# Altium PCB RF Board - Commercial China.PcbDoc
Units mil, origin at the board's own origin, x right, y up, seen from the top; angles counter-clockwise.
Board outline 2000 x 1000 mil, 2 copper layers (Top Layer, Bottom Layer); 17 components, 17 nets, 58 pads, 9 vias.
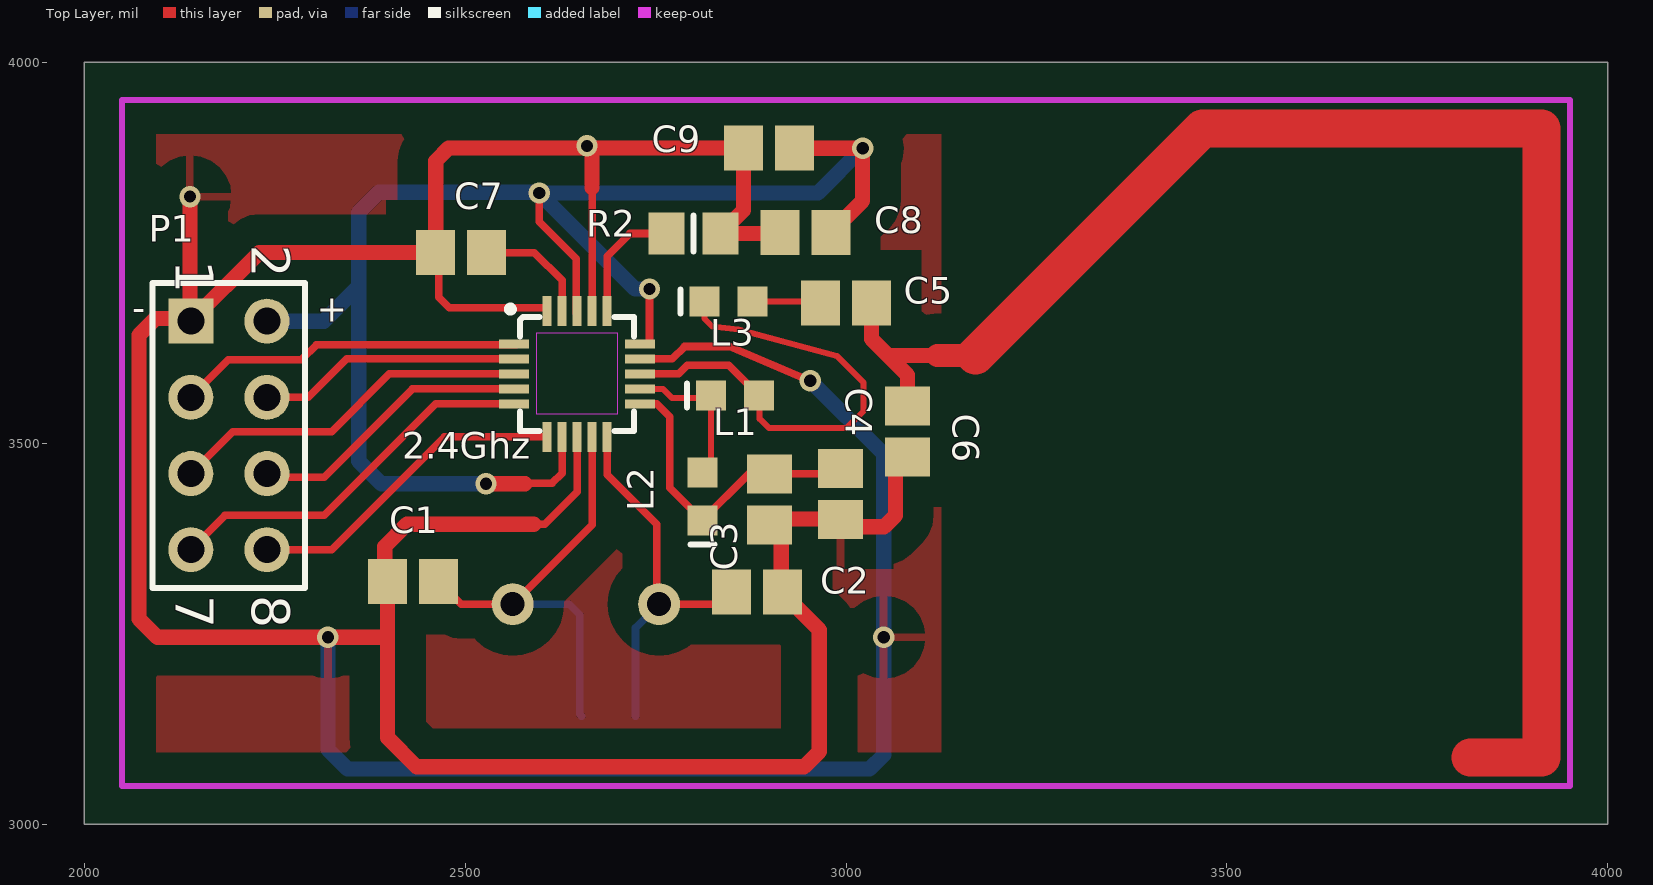
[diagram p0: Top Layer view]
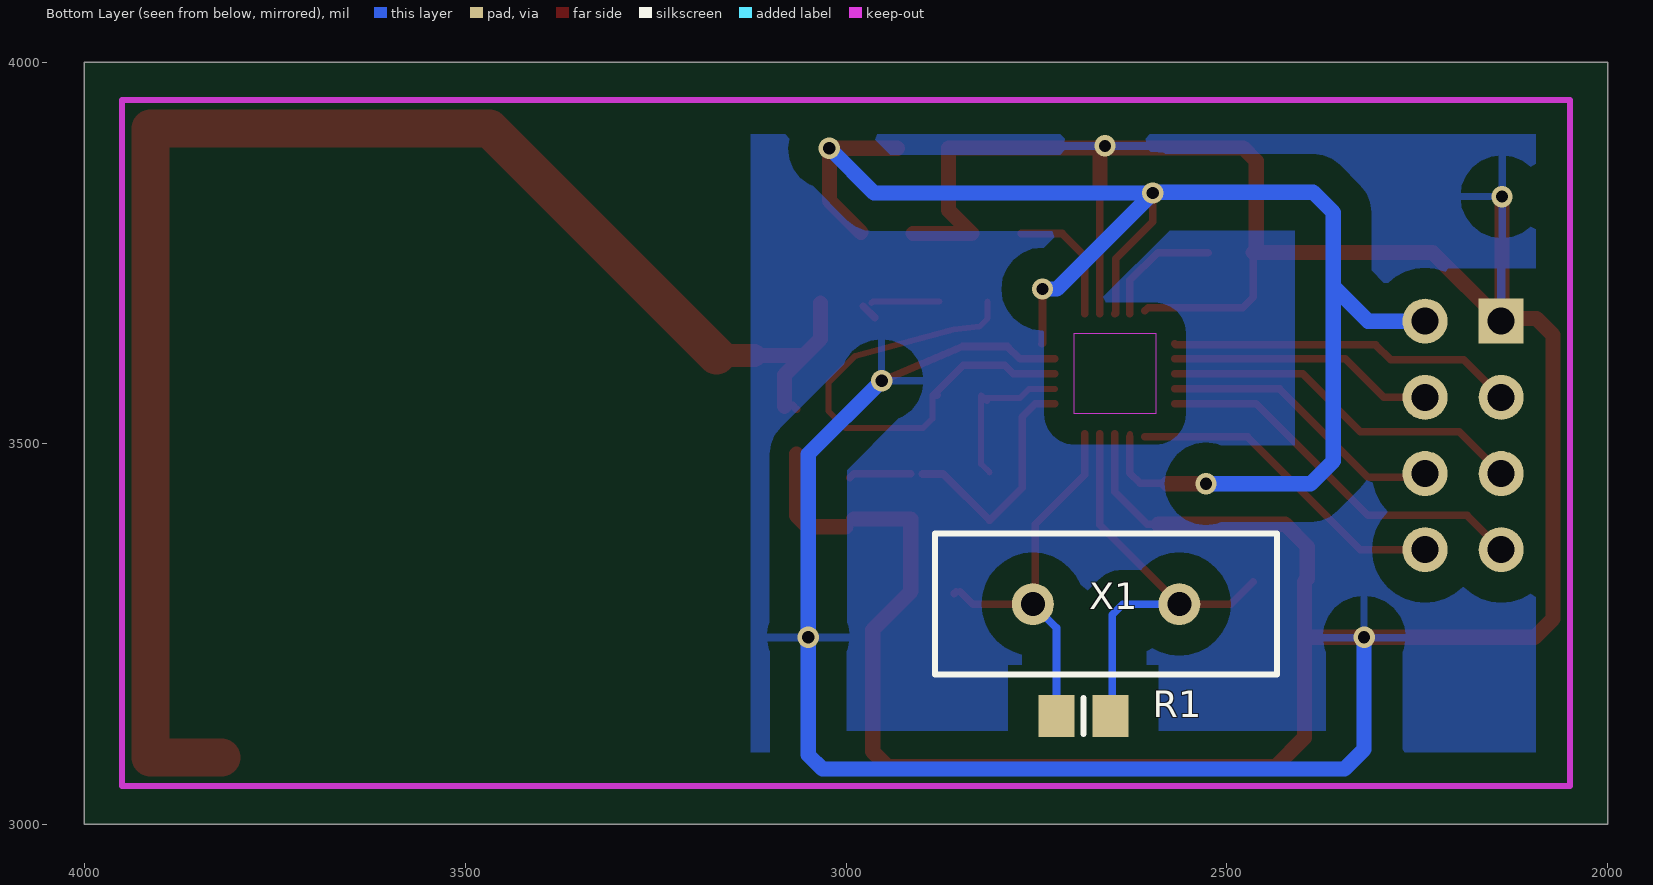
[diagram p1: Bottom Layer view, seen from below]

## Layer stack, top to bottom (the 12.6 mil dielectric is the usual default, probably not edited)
Top Layer: signal copper 1.4
Dielectric: dielectric 12.6, FR-4, Dk 4.8
Bottom Layer: signal copper 1.4

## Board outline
2000,3000 4000,3000 4000,4000 2000,4000

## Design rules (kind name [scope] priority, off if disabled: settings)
Clearance "Polygon Clearance" [InPolygon] p1: gap=40
Clearance [All] p2: gap=8.1
HoleSize [All] p1: absolutevalues=TRUE maxlimit=100 minlimit=16 maxpercent=80.000 minpercent=20.000
MinimumAnnularRing [All] p1: minimumring=6
PolygonConnect [All] p1: connectstyle=Relief reliefconductorwidth=10 reliefentries=4 polygonreliefangle="90 Angle"
RoutingVias [All] p1: holewidth=16 width=28 viastyle="Through Hole" minholewidth=16 minwidth=27 maxholewidth=16 maxwidth=35
SilkscreenOverComponentPads [All] p1: minsilkscreentomaskgap=10
SolderMaskExpansion [All] p1: expansion=4
Width [All] p1: maxlimit=50 minlimit=8 preferedwidth=8
26 further rules are at their usual default settings.

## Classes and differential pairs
component class "2.4Ghz Chip Board": P1
net class SPI[3..0]: SPI0 SPI1 SPI2 SPI3

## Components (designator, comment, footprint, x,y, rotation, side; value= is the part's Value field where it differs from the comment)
2.4Ghz "nRF24L01+" nRF24L01+ 2576.16,3630.12 r0 top (schematic designator "2.4Ghz Chip")
C1 "Cap Semi" CAPC2012N 2431.81,3318.02 r0 top
C2 "Cap Semi" CAPC2012N 2883.35,3304.68 r180 top
C3 "Cap Semi" CAPC2012N 2899.64,3425.9 r90 top
C4 "Cap Semi" CAPC2012N 2992.87,3433.15 r90 top
C5 "Cap Semi" CAPC2012N 3000.12,3683.85 r180 top
C6 "Cap Semi" CAPC2012N 3080.62,3514.92 r90 top
C7 "Cap Semi" CAPC2012N 2495,3750 r0 top
C8 "Cap Semi" CAPC2012N 2946.88,3776.47 r0 top
C9 "Cap Semi" CAPC2012N 2899.02,3887.01 r0 top
L1 "Inductor" INDC1608N 2854.06,3562.65 r0 top
L2 "Inductor" INDC1608N 2811.58,3430.04 r90 top
L3 "Inductor" INDC1608N 2845.77,3685.93 r0 top
P1 "Header 4X2" HDR2X4 2140,3660 r270 top
R1 "Res2" RESC2012N 2688.35,3141.5 r0 bottom
R2 "Res3" RESC2012N 2799.53,3775 r0 top
X1 "16Mhz" "HC-49U - Through Hole" 2658.63,3288.52 r0 bottom

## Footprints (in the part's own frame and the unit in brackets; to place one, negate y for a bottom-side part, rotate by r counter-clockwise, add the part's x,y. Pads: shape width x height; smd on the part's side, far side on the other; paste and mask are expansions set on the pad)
CAPC2012N [mm] "Chip Capacitor, Body 2.0x1.3mm, IPC Medium Density"
  rect 1.3x1.5 smd: 1(-0.85,0) 2(0.85,0)
  body extent -1.1,-0.72 1.1,0.72, height 1.1
"HC-49U - Through Hole" [mm] "Quartz Crystal, Thru-Hole; 2 Leads; Body 11.35 x 4.65 x 13.46 mm (LxWxH max)"
  round 1.4 hole 0.8: 1(-2.44,0) 2(2.44,0)
  silkscreen extent -5.7,-2.35 5.7,2.35
HDR2X4 [mm] "Connector; Header; 4x2 Position"
  rect 1.5x1.5 hole 0.9: 1(0,0)
  round 1.5 hole 0.9: 2(0,2.54) 3(2.54,0) 4(2.54,2.54) 5(5.08,0) 6(5.08,2.54) 7(7.62,0) 8(7.62,2.54)
  silkscreen extent -1.27,-1.27 8.89,3.81
INDC1608N [mm] "Chip Inductor, Body 1.6x0.8mm, IPC Medium Density"
  rect 1x1 smd: 1(-0.8,0) 2(0.8,0)
  silkscreen extent -1.6,-0.4 -1.6,0.4, body extent -0.87,-0.48 0.87,0.48, height 0.71
nRF24L01+ [mm]
  rect 1x0.29 smd: 1(-0.3,0) 2(-0.3,-0.5) 3(-0.3,-1) 4(-0.3,-1.5) 5(-0.3,-2) 11(3.9,-2) 12(3.9,-1.5) 13(3.9,-1) 14(3.9,-0.5) 15(3.9,0)
  rect 0.29x1 smd: 6(0.8,-3.1) 7(1.3,-3.1) 8(1.8,-3.1) 9(2.3,-3.1) 10(2.8,-3.1) 16(2.8,1.1) 17(2.3,1.1) 18(1.8,1.1) 19(1.3,1.1) 20(0.8,1.1)
  Keep-Out Layer region: 0.447,-2.334 3.152,-2.334 3.152,0.357 0.447,0.357
  silkscreen extent -0.49,-2.9 3.7,1.22
RESC2012N [mm] "Chip Resistor, Body 2.0x1.3mm, IPC Medium Density"
  rect 1.2x1.4 smd: 1(-0.9,0) 2(0.9,0)
  silkscreen extent 0,-0.6 0,0.6, body extent -1.07,-0.7 1.07,0.7, height 0.65

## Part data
C1 C2 C3 C4 C5 C6 C7 C8 C9: "Capacitor (Semiconductor SIM Model)"
P1: "Header, 4-Pin, Dual row"
R1 R2: "Resistor"
X1: library part XTAL, "Crystal Oscillator"

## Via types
v1: diameter 28, hole 16, Top Layer to Bottom Layer, 9 vias

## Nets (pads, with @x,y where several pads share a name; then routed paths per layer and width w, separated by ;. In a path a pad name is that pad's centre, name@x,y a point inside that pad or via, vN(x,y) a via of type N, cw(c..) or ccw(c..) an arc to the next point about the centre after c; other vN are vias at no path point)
3.3VCC: 2.4Ghz.7 2.4Ghz.15 2.4Ghz.18 C8.2 C9.2 P1.2 | length 2171.9
  Top Layer w8: 2.4Ghz.7 2.4Ghz.7@2627.34,3512.01
  Top Layer w10: 2579.2,3446.99 2614.06,3446.99 2627.34,3460.27 2.4Ghz.7 ; v1(2597.29,3828.13) 2597.29,3790.56 2646.15,3741.7 2646.15,3670.37 2.4Ghz.18@2647.03,3669.49 ; v1(2742.08,3702.14) 2742.08,3631.08 2.4Ghz.15@2743.04,3630.12 ; v1@3021.77,3887.01 v1(3021.88,3886.9)
  Top Layer w20: v1(2527.51,3446.52) 2578.73,3446.52 ; C9.2 3021.77,3887.01 3021.77,3817.9 C8.2
  Bottom Layer w20: P1.2@2245,3665 P1.2 2314.81,3660 2360.4,3705.59 ; v1(2527.51,3446.52) 2390.27,3446.52 2360.4,3476.39 2360.4,3705.59 ; v1(2742.08,3702.14) 2723.28,3702.14 v1(2597.29,3828.13) ; v1(3021.88,3886.9) 2963.11,3828.13 v1(2597.29,3828.13) ; 2360.4,3705.59 2360.4,3802.76 2386.94,3829.3 2596.12,3829.3 v1(2597.29,3828.13)
CE: 2.4Ghz.1 P1.3 | length 457.3
  Top Layer w10: P1.3 2189.34,3609.34 2285.16,3609.34 2305.06,3629.24 2567.41,3629.24 2.4Ghz.1@2568.29,3630.12
GND: 2.4Ghz.8 2.4Ghz.14 2.4Ghz.17 2.4Ghz.20 C1.1 C2.1 C3.1 C4.1 C6.1 C7.1 C8.1 C9.1 P1.1 R2.2 | length 5941
  Top Layer w10: C7.1@2465.47,3750 2465.47,3691.6 2479.38,3677.69 2603.39,3677.69 2.4Ghz.20 ; 2590.13,3393.53 2604.63,3393.53 2647.03,3435.93 2.4Ghz.8 2.4Ghz.8@2647.03,3512.01 ; 2.4Ghz.17@2666.71,3669.49 2.4Ghz.17 2666.71,3835 ; 2.4Ghz.14@2725.77,3610.43 2.4Ghz.14 2771.89,3610.43 2788.11,3626.66 2847.13,3626.66 2847.19,3626.59 v1(2953.17,3581.7) ; C8.1@2911.95,3775 C8.1 ; C2.1@2914.53,3305 C2.1@2915,3305.47 ; C4.1@2990,3400.47 C4.1@3000.47,3390
  Top Layer w20: v1(2139,3823.46) P1.1@2139,3661 ; 2423.75,3393.52 2394.6,3364.37 2394.6,3321.77 C1.1 2398.35,3244.28 ; 2423.75,3393.53 2590.13,3393.53 ; C7.1@2465.47,3750 C7.1 ; 2666.71,3835 2666.71,3883.29 v1@2662.87,3887.13 ; C8.1@2911.95,3775 R2.2 2865.56,3805.59 C9.1 2865.44,3887.13 v1@2662.87,3887.13 ; C2.1@2914.53,3305 2965,3254.53 2965,3095 2945,3075 2436.63,3075 2398.35,3113.28 2398.35,3244.28 ; C2.1@2915,3305.47 2915,3400.47 C4.1@2990,3400.47 ; C4.1@3000.47,3390 3050,3390 3065,3405 C6.1@3065,3485.47 ; P1.1@2139,3661 2131.71,3653.71 P1.1 ; P1.1@2139,3661 2136.69,3663.31 2093.71,3663.31 2072.1,3641.7 2072.1,3269.2 2096.3,3245 v1(2320,3245) 2397.63,3245 2398.35,3244.28 ; P1.1@2139,3661 P1.1 ; P1.1 2230,3750 C7.1 ; C7.1 2461.54,3870.29 2478.38,3887.13 v1@2660,3887.13 ; v1@2660,3887.13 v1(2660,3890) v1@2662.87,3887.13 ; v1@2660,3887.13 v1@2662.87,3887.13
  Bottom Layer w20: v1(2320,3245) 2320,3097.79 2345.69,3072.1 3030.85,3072.1 3049.61,3090.86 v1(3049.61,3245.14) 3049.61,3485.26 v1(2953.17,3581.7)
IRQ: 2.4Ghz.6 P1.8 | length 429
  Top Layer w10: P1.8 2325,3360 2473.07,3508.07 2.4Ghz.6
"Net2.4Ghz Chip_9": 2.4Ghz.9 C1.2 R1.1 X1.1 | length 604.1
  Top Layer w10: C1.2 2494.77,3288.52 X1.1 2666.71,3392.66 2.4Ghz.9 2.4Ghz.9@2666.71,3512.01
  Bottom Layer w10: X1.1 2636.8,3288.52 2650.45,3274.87 2650.45,3143.97 R1.1
"Net2.4Ghz Chip_10": 2.4Ghz.10 C2.2 R1.2 X1.2 | length 517
  Top Layer w10: 2.4Ghz.10@2686.4,3512.01 2.4Ghz.10 2686.4,3458.6 2751.59,3393.41 2751.59,3291.63 X1.2 2833.73,3288.52 C2.2 ; C2.2@2855.47,3305 C2.2@2857.99,3302.48
  Bottom Layer w10: R1.2 2723.78,3257.61 X1.2
"Net2.4Ghz Chip_11": 2.4Ghz.11 C3.2 C4.2 L2.1 | length 399
  Top Layer w10: 2.4Ghz.11@2725.77,3551.38 2751.83,3551.38 2768.58,3534.63 2768.58,3441.54 L2.1 2872.4,3459.36 C3.2 ; C3.2@2915,3459.53 2990,3459.53 C4.2@2995,3454.53
"Net2.4Ghz Chip_12": 2.4Ghz.12 L1.1 L2.2 | length 214.1
  Top Layer w8: 2.4Ghz.12@2725.77,3571.07 2759.6,3571.07 2771.76,3558.9 L1.1@2818.81,3558.9 ; L2.2 2822.56,3472.52 L1.1 L1.1@2818.81,3558.9 ; L1.1@2815.23,3555.32 L1.1@2818.81,3558.9
"Net2.4Ghz Chip_13": 2.4Ghz.13 L1.2 L3.1 | length 666.4
  Top Layer w8: L3.1 2814.27,3663.43 2824.77,3652.93 2858.77,3648.91 2987.86,3614.45 3023.13,3579.18 3023.13,3542.06 3000.89,3519.82 2898.77,3519.82 2886.66,3531.93 2886.66,3561.55 L1.2 2880.46,3562.65 L1.2@2879.05,3562.65
  Top Layer w10: 2.4Ghz.13@2725.77,3590.75 2780.68,3590.75 2791.88,3601.95 2846.26,3601.95 L1.2 L1.2@2880.46,3562.65
"Net2.4Ghz Chip_16": 2.4Ghz.16 R2.1 | length 171.6
  Top Layer w10: 2.4Ghz.16@2686.4,3669.49 2686.4,3745.06 2716.34,3775 R2.1@2770,3775
"Net2.4Ghz Chip_19": 2.4Ghz.19 C7.2 | length 162
  Top Layer w10: C7.2@2524.53,3750 2590.98,3750 2627.34,3713.64 2.4Ghz.19 2.4Ghz.19@2627.34,3669.49
NetC5_1: C5.1 C6.2 | length 2062
  Top Layer w10: C6.2@3065,3544.53 C6.2@3070,3549.53
  Top Layer w20: C5.1 3033.58,3636.42 3055,3615 ; C6.2 3080.62,3589.38 3055,3615 ; 3120,3615 3055,3615
  Top Layer w30: 3120,3615 3170,3615
  Top Layer w50: 3170,3615 3467.9,3912.9 3912.9,3912.9 3912.9,3087.1 3820,3087.1
NetC5_2: C5.2 L3.2 | length 111.2
  Top Layer w8: L3.2 2964.58,3685.93 C5.2
  Top Layer w10: C5.2@2962.42,3664.8 C5.2@2977.23,3679.61
SPI0: 2.4Ghz.2 P1.4 | length 349.2
  Top Layer w10: P1.4 2294.34,3560 2344.77,3610.43 2.4Ghz.2@2568.29,3610.43
SPI1: 2.4Ghz.3 P1.5 | length 482.4
  Top Layer w10: P1.5 2195,3515 2325,3515 2400.75,3590.75 2.4Ghz.3@2568.29,3590.75
SPI2: 2.4Ghz.4 P1.6 | length 378.4
  Top Layer w10: P1.6 2245,3455 2315,3455 2431.07,3571.07 2.4Ghz.4@2568.29,3571.07
SPI3: 2.4Ghz.5 P1.7 | length 507.6
  Top Layer w10: P1.7 2185,3405 2315,3405 2461.38,3551.38 2.4Ghz.5@2568.29,3551.38

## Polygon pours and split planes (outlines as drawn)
GND on Bottom Layer "Bottom Layer-No Net" (solid, pour order 2): 2025,3980 2030,3975 3125,3975 3125,3025 2025,3025
GND on Top Layer "Top Layer-GND" (solid, pour order 4): 2025,3975 3125,3975 3125,3025 2025,3025

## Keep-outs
Keep-Out Layer:
  lines w8: 2050,3050 3950,3050 3950,3950 2050,3950 2050,3050

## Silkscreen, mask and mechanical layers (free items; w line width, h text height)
Top Overlay:
  text "-" at 2062.89,3649.58 h60
  text "+" at 2305.63,3647.36 h60
Drill Drawing:
  text ".LEGEND" at 4200,3200 h60
  text "Drill Drawing." at 4200,3100 h60

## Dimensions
2050,3050 to 3950,3050 on Mechanical 1
2050,3050 to 2050,3950 on Mechanical 1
